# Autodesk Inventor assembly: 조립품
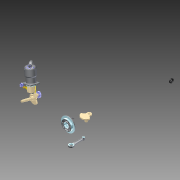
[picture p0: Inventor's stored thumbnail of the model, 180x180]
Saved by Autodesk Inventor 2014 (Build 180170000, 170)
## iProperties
Created: 2015-06
Part Number: 조립품
Document SubType Name: Assembly
Designer: user
Author: user
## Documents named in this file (15)
- C:\Users\user\Desktop\450606v1011\조립품.iam
- C:\Users\user\Desktop\분할장치\본체.ipt
- C:\Users\user\Desktop\450606v1011\M4x0.7.ipt
- C:\Users\user\Desktop\450606v1011\M5x0.8.ipt
- C:\Users\user\Desktop\450606v1011\메인 크랭크 축-구동부.ipt
- C:\Users\user\Desktop\450606v1011\메인커버.ipt
- C:\Users\user\Desktop\450606v1011\베어링 6204.ipt
- C:\Users\user\Desktop\450606v1011\베어링 NA 4902.ipt
- C:\Users\user\Desktop\450606v1011\실린더.ipt
- C:\Users\user\Desktop\450606v1011\실린더헤드.ipt
- C:\Users\user\Desktop\450606v1011\오일실.ipt
- C:\Users\user\Desktop\450606v1011\커넥팅 로드.ipt
- C:\Users\user\Desktop\450606v1011\크랭크 서브축.ipt
- C:\Users\user\Desktop\450606v1011\피스톤 핀.ipt
- C:\Users\user\Desktop\450606v1011\피스톤.ipt
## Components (4 placed, 4 different names)
1. M4x0.7:1
2. M5x0.8:1
3. 피스톤 핀:1 — Mate:3
4. 피스톤:2 — Insert:4, Mate:3
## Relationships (2: Insert 1, Mate 1)
- Insert:4: 피스톤:2
- Mate:3: 피스톤 핀:1 ↔ 피스톤:2
